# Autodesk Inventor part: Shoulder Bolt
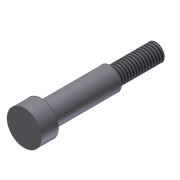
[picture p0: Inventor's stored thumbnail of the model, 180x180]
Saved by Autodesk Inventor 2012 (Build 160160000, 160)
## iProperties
Created: 2011-12
Part Number: Shoulder Bolt
Document SubType Name: Modeling
Designer: OSR
Density: 8.08 g/cm^3
Material: Stainless Steel
Mass: 9.91618 g
Surface Area: 8.90538 cm^2
Volume: 1.22725 cm^3
Author: OSR
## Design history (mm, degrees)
sketch "Sketch2"
  geometry: L1 (0, 0)-(4.763, 0); L2 (4.763, 0)-(4.763, -4.763); L3 (4.763, -4.763)-(3.175, -4.763); L4 (3.175, -4.763)-(3.175, -23.812); L5 (3.175, -23.812)-(2.413, -23.812); L6 (2.413, -23.812)-(2.413, -36.513); L7 (2.413, -36.513)-(0, -36.513); L8 (0, -36.513)-(0, 0)
  constraints: 16 end point, 5 parallel, 2 perpendicular, 1 horizontal
  dimensions: "d1" = 19.05 distance of L3.end L4.end; "d2" = 3.175 distance between parallel lines of L8 L4; "d3" = 2.413 distance between parallel lines of L8 L6; "d4" = 4.7625 distance of L1.end L2.end; "d5" = 4.7625 distance of L1.start L1.end; "d9" = 12.7 distance of L5.end L6.end
revolve "Revolution1" sketch "Sketch2" stored, may be unused: angle "d6" = 90 deg
thread "Thread1" dims "d7" = 25.4, "d8" = 0
body "Solid1"
